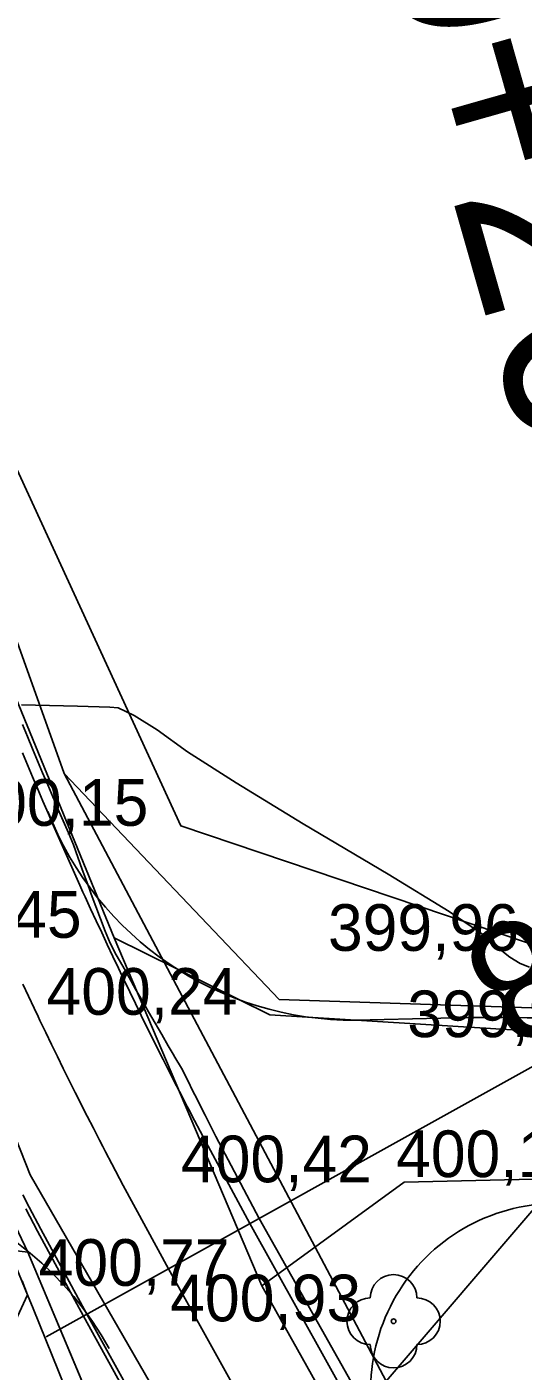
# Model space of a CAD drawing. Extents: x -574342 to -507939, y -1144044 to -1123894.
# Drawn here: x -508531.96 to -508521.32, y -1143262.87 to -1143234.06 of the extents above; entities that cross this region are included whole.
import ezdxf

# ---------------------------------------------------------------- set-up
doc = ezdxf.new("R2010")
doc.units = 0
for name, color, linetype in [('01_PARCELY_NAVRH_PC', 7, 'Continuous'), ('01_PARCELY_NAVRH_VHO', 7, 'Continuous'), ('01_PARCELY_NAVRH_ŽP', 7, 'Continuous'), ('1000', 7, 'Continuous'), ('18', 7, 'Continuous'), ('21', 7, 'Continuous'), ('23', 7, 'Continuous'), ('37', 7, 'Continuous'), ('42', 7, 'Continuous'), ('54', 7, 'Continuous'), ('55', 7, 'Continuous'), ('cesty', 7, 'Continuous'), ('Level 255', 7, 'Continuous'), ('propustek', 7, 'Continuous'), ('VRST HL', 7, 'Continuous')]:
    doc.layers.add(name, color=color, linetype=linetype)

msp = doc.modelspace()

# ---------------------------------------------------------------- linework, layer by layer
at = {"layer": '01_PARCELY_NAVRH_PC'}
for points in [[(-508524.61, -1143277.77), (-508531.94, -1143260.32), (-508534.5, -1143254.93), (-508536.24, -1143250.83), (-508539.07, -1143243.44), (-508539.77, -1143241.25), (-508540.55, -1143238.43), (-508542.83, -1143228.38), (-508544.32, -1143217.47), (-508545.45, -1143205.07), (-508545.52, -1143198.58), (-508545.24, -1143191.32), (-508544.97, -1143188.3), (-508544.25, -1143181.83), (-508541.94, -1143173.53), (-508537.18, -1143176.51), (-508538.65, -1143182.46), (-508540.32, -1143193.28), (-508540.02, -1143209.35), (-508538.46, -1143221.35), (-508537.02, -1143231.11), (-508535.34, -1143238.37), (-508531.16, -1143250.06), (-508524.26, -1143263.08)], [(-508524.61, -1143277.77), (-508531.94, -1143260.32), (-508534.5, -1143254.93), (-508536.24, -1143250.83), (-508539.07, -1143243.44), (-508539.77, -1143241.25), (-508540.55, -1143238.43), (-508542.83, -1143228.38), (-508544.32, -1143217.47), (-508545.45, -1143205.07), (-508545.52, -1143198.58), (-508545.24, -1143191.32), (-508544.97, -1143188.3), (-508544.25, -1143181.83), (-508541.94, -1143173.53), (-508537.18, -1143176.51), (-508538.65, -1143182.46), (-508540.32, -1143193.28), (-508540.02, -1143209.35), (-508538.46, -1143221.35), (-508537.02, -1143231.11), (-508535.34, -1143238.37), (-508531.16, -1143250.06), (-508524.26, -1143263.08)], [(-508866.763, -1143529.283), (-508859.41, -1143516.97), (-508810.66, -1143431.99), (-508773.29, -1143386.75), (-508766.4, -1143380.31), (-508664.99, -1143316.89), (-508539, -1143259.35), (-508535.36, -1143259.89), (-508531.94, -1143260.32), (-508534.5, -1143254.93), (-508536.24, -1143250.83), (-508538.24, -1143253.15), (-508539.95, -1143255.3), (-508667.19, -1143313.15), (-508770.98, -1143377.64), (-508813.09, -1143427.79), (-508861.39, -1143510.97), (-508866.763, -1143520.059)]]:
    msp.add_lwpolyline(points, dxfattribs=at)
msp.add_lwpolyline([(-508446.21, -1143255.76), (-508469.74, -1143257.73), (-508480.76, -1143258.08), (-508496.39, -1143258.35), (-508520.28, -1143255.11), (-508526.55, -1143254.9), (-508531.16, -1143250.06), (-508524.26, -1143263.08), (-508521.01, -1143259.29), (-508514.56, -1143259.91), (-508493.5, -1143263.3), (-508475.11, -1143263.39), (-508446.02, -1143260.22)], close=True, dxfattribs=at)
at = {"layer": '01_PARCELY_NAVRH_VHO'}
msp.add_lwpolyline([(-508497.13, -1143495.86), (-508497.34, -1143500.64), (-508499.94, -1143496.07), (-508501.52, -1143472.9), (-508509.71, -1143373.98), (-508513.61, -1143343.97), (-508516.21, -1143324.53), (-508518.91, -1143309.47), (-508522.63, -1143293.85), (-508527.23, -1143279.34), (-508534.32, -1143262.4), (-508535.36, -1143259.89), (-508531.94, -1143260.32), (-508524.61, -1143277.77), (-508522.34, -1143283.22), (-508517.78, -1143295.12), (-508517.67, -1143298.65), (-508514.79, -1143310.81), (-508512.2, -1143325.42), (-508505.85, -1143384.53), (-508502.4, -1143424.77), (-508500.25, -1143457.08), (-508499.28, -1143468.17)], close=True, dxfattribs=at)
at = {"layer": '01_PARCELY_NAVRH_ŽP'}
msp.add_lwpolyline([(-508425.23, -1143400.39), (-508448.26, -1143343.08), (-508432.21, -1143324.29), (-508434.31, -1143320.59), (-508441.9, -1143297.61), (-508445.4, -1143275.01), (-508446.02, -1143260.22), (-508475.11, -1143263.39), (-508493.5, -1143263.3), (-508514.56, -1143259.91), (-508521.01, -1143259.29), (-508524.26, -1143263.08), (-508519.86, -1143267.33), (-508511.25, -1143285.64), (-508506.89, -1143298.29), (-508504.21, -1143312.1), (-508498.26, -1143372.94), (-508491.36, -1143454.58)], dxfattribs=at)
at = {"layer": '1000'}
for points in [[(-508532.052, -1143249.01), (-508531.946, -1143249.269), (-508531.838, -1143249.527), (-508531.73, -1143249.786), (-508531.622, -1143250.044), (-508531.512, -1143250.302), (-508531.402, -1143250.559), (-508531.347, -1143250.688), (-508531.292, -1143250.817), (-508531.18, -1143251.074), (-508531.069, -1143251.331), (-508530.962, -1143251.59), (-508530.867, -1143251.854), (-508530.771, -1143252.118), (-508530.675, -1143252.382), (-508530.618, -1143252.536), (-508530.578, -1143252.646), (-508530.48, -1143252.91), (-508530.381, -1143253.173), (-508530.282, -1143253.436), (-508530.173, -1143253.695), (-508530.041, -1143253.943), (-508529.904, -1143254.188), (-508529.811, -1143254.352), (-508529.766, -1143254.433), (-508529.628, -1143254.678), (-508529.489, -1143254.922), (-508529.349, -1143255.166), (-508529.209, -1143255.409), (-508529.068, -1143255.652), (-508528.927, -1143255.895), (-508528.82, -1143256.078), (-508528.785, -1143256.137), (-508528.642, -1143256.378), (-508528.513, -1143256.627), (-508528.391, -1143256.879), (-508528.326, -1143257.012), (-508528.267, -1143257.13), (-508528.14, -1143257.38), (-508527.906, -1143257.839), (-508526.979, -1143259.594), (-508521.572, -1143269.197)], [(-508532.051, -1143249.615), (-508531.943, -1143249.875), (-508531.834, -1143250.133), (-508531.725, -1143250.392), (-508531.615, -1143250.65), (-508531.56, -1143250.779), (-508531.504, -1143250.908), (-508531.393, -1143251.166), (-508531.28, -1143251.423), (-508531.167, -1143251.68), (-508531.053, -1143251.937), (-508530.939, -1143252.193), (-508530.824, -1143252.449), (-508530.756, -1143252.599), (-508530.708, -1143252.705), (-508530.591, -1143252.961), (-508530.474, -1143253.216), (-508530.355, -1143253.47), (-508530.236, -1143253.725), (-508530.117, -1143253.979), (-508529.996, -1143254.232), (-508529.915, -1143254.402), (-508529.875, -1143254.486), (-508529.754, -1143254.739), (-508529.631, -1143254.991), (-508529.508, -1143255.244), (-508529.384, -1143255.495), (-508529.259, -1143255.747), (-508529.134, -1143255.998), (-508529.038, -1143256.188), (-508529.008, -1143256.249), (-508528.881, -1143256.5), (-508528.753, -1143256.75), (-508528.625, -1143256.999), (-508528.557, -1143257.131), (-508528.496, -1143257.249), (-508528.366, -1143257.498), (-508528.125, -1143257.956), (-508527.177, -1143259.704), (-508521.823, -1143269.337)], [(-508532.046, -1143259.092), (-508531.911, -1143259.351), (-508531.66, -1143259.827), (-508530.673, -1143261.647), (-508525.32, -1143271.28)], [(-508531.982, -1143259.388), (-508531.731, -1143259.865), (-508530.747, -1143261.689), (-508525.433, -1143271.343)], [(-508529.625, -1143266.969), (-508531.822, -1143261.526), (-508531.942, -1143261.23), (-508532.062, -1143260.935)]]:
    msp.add_lwpolyline(points, dxfattribs=at)
at = {"layer": '21'}
msp.add_lwpolyline([(-508532.047, -1143254.574), (-508531.925, -1143254.833), (-508531.802, -1143255.092), (-508531.719, -1143255.266), (-508531.679, -1143255.351), (-508531.554, -1143255.609), (-508531.429, -1143255.867), (-508531.304, -1143256.124), (-508531.177, -1143256.381), (-508531.05, -1143256.638), (-508530.922, -1143256.894), (-508530.825, -1143257.088), (-508530.793, -1143257.15), (-508530.664, -1143257.406), (-508530.533, -1143257.661), (-508530.403, -1143257.916), (-508530.333, -1143258.05), (-508530.271, -1143258.17), (-508530.139, -1143258.424), (-508529.893, -1143258.891), (-508528.925, -1143260.676), (-508523.571, -1143270.308)], dxfattribs=at)
at = {"layer": '23'}
for points in [[(-508528.925, -1143260.676), (-508505.325, -1143247.56)], [(-508528.925, -1143260.676), (-508531.547, -1143262.133)]]:
    msp.add_lwpolyline(points, dxfattribs=at)
at = {"layer": '37'}
for points in [[(-508544.44, -1143182.59), (-508545.29, -1143193.14), (-508544.8, -1143205.6), (-508541.6, -1143228.19), (-508538.07, -1143243), (-508531.89, -1143258.66), (-508522.3, -1143275.29), (-508518.1, -1143283.75), (-508512.73, -1143299.25), (-508510.49, -1143313.12)], [(-508544.44, -1143182.59), (-508545.29, -1143193.14), (-508544.8, -1143205.6), (-508541.6, -1143228.19), (-508538.07, -1143243), (-508531.89, -1143258.66), (-508522.3, -1143275.29), (-508518.1, -1143283.75), (-508512.73, -1143299.25), (-508510.49, -1143313.12)], [(-508507.09, -1143312.37), (-508509.64, -1143298.16), (-508515.1, -1143282.44), (-508519.8, -1143273.76), (-508526.92, -1143261.04), (-508530.09, -1143253.58), (-508534.91, -1143241.83), (-508538.52, -1143226.92), (-508541.3, -1143204.98), (-508541.88, -1143193.39), (-508540.68, -1143183.59)], [(-508507.09, -1143312.37), (-508509.64, -1143298.16), (-508515.1, -1143282.44), (-508519.8, -1143273.76), (-508526.92, -1143261.04), (-508530.09, -1143253.58), (-508534.91, -1143241.83), (-508538.52, -1143226.92), (-508541.3, -1143204.98), (-508541.88, -1143193.39), (-508540.68, -1143183.59)]]:
    msp.add_lwpolyline(points, dxfattribs=at)
at = {"layer": '42'}
msp.add_lwpolyline([(-508475.71, -1143257.35), (-508496.39, -1143258.35), (-508520.72, -1143253.86), (-508528.66, -1143251.18), (-508534.38, -1143238.75), (-508538.15, -1143218.95), (-508538.33, -1143193.52)], dxfattribs=at)
msp.add_lwpolyline([(-508475.71, -1143257.35), (-508496.39, -1143258.35), (-508520.72, -1143253.86), (-508528.66, -1143251.18), (-508534.38, -1143238.75), (-508538.15, -1143218.95), (-508538.33, -1143193.52)], dxfattribs=at)
at = {"layer": '54'}
msp.add_circle((-508524.1, -1143261.8), 0.05, dxfattribs=at)
for centre, start, end in [((-508524.1, -1143261.3), 0, 180), ((-508524.6, -1143261.8), 90, 270), ((-508523.6, -1143261.8), 270, 90), ((-508524.1, -1143262.3), 180, 0)]:
    msp.add_arc(centre, 0.5, start, end, dxfattribs=at)
at = {"layer": '55'}
for points in [[(-508530.09, -1143253.58), (-508526.75, -1143255.23), (-508519.02, -1143255.71), (-508495.48, -1143259.17)], [(-508530.09, -1143253.58), (-508526.75, -1143255.23), (-508519.02, -1143255.71), (-508495.48, -1143259.17)], [(-508495.8, -1143262.63), (-508519.26, -1143258.71), (-508523.87, -1143258.82), (-508526.92, -1143261.04)], [(-508495.8, -1143262.63), (-508519.26, -1143258.71), (-508523.87, -1143258.82), (-508526.92, -1143261.04)]]:
    msp.add_lwpolyline(points, dxfattribs=at)
at = {"layer": 'cesty'}
msp.add_line((-508522.478, -1143255.29), (-508524.906, -1143255.345), dxfattribs=at)
for centre, radius, start, end in [((-508524.979, -1143248.345), 7, 201.1483, 270.6015), ((-508521.984, -1143302.287), 47, 80.9307, 90.6015), ((-508536.338, -1143265.744), 7, 28.6901, 114.5203), ((-508520.592, -1143263.271), 4, 90.6015, 208.6901)]:
    msp.add_arc(centre, radius, start, end, dxfattribs=at)
at = {"layer": 'propustek'}
msp.add_lwpolyline([(-508534.334, -1143261.705), (-508534.637, -1143260.968), (-508534.941, -1143260.23), (-508535.306, -1143259.345), (-508535.421, -1143258.804), (-508534.03, -1143259.135), (-508533.766, -1143259.233), (-508533.127, -1143259.523), (-508532.501, -1143259.889), (-508532.186, -1143260.641), (-508531.942, -1143261.23), (-508532.29, -1143261.978), (-508532.917, -1143262.503), (-508533.351, -1143262.379)], close=True, dxfattribs=at)
at = {"layer": 'VRST HL'}
msp.add_lwpolyline([(-508532.075, -1143248.587), (-508530.874, -1143248.619), (-508530.183, -1143248.64), (-508530.001, -1143248.65), (-508529.662, -1143248.812), (-508529.166, -1143249.126), (-508528.514, -1143249.592), (-508527.471, -1143250.262), (-508526.038, -1143251.137), (-508524.215, -1143252.216), (-508522.909, -1143253.02), (-508522.122, -1143253.549), (-508521.851, -1143253.802), (-508521.606, -1143253.997), (-508521.386, -1143254.134), (-508521.19, -1143254.213)], dxfattribs=at)

# ---------------------------------------------------------------- texts
at = {"layer": '18'}
for s, height, rotation, p in [('0+200', 4, 285.897, (-508524.54, -1143231.773)), ('KT0+222.98', 2.5, 209.0636, (-508506.782, -1143244.938))]:
    msp.add_text(s, height=height, rotation=rotation, dxfattribs=at).set_placement(p)
at = {"layer": 'Level 255'}
for s, p in [('400,15', (-508533.445, -1143251.18)), ('400,45', (-508534.875, -1143253.58)), ('399,96', (-508525.505, -1143253.86)), ('400,24', (-508531.535, -1143255.23)), ('399,96', (-508523.805, -1143255.71)), ('400,42', (-508528.655, -1143258.82)), ('400,12', (-508524.045, -1143258.71)), ('400,77', (-508531.705, -1143261.04)), ('400,93', (-508528.885, -1143261.8))]:
    msp.add_text(s, height=1, dxfattribs=at).set_placement(p)

doc.saveas('drawing.dxf')
